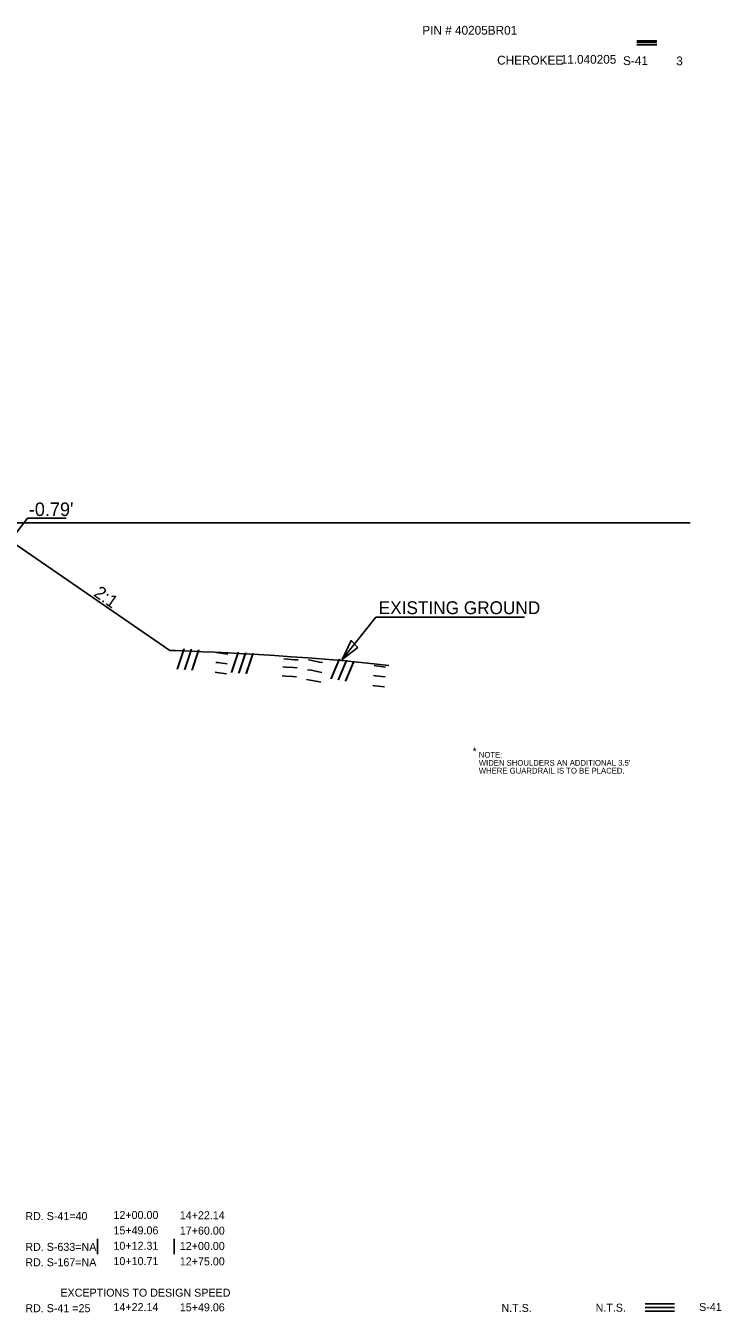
# Model space of a CAD drawing. Extents: x 2061536 to 2063199, y 948597 to 949645.
# Drawn here: x 2062634 to 2063199, y 948600 to 949645 of the extents above; entities that cross this region are included whole.
import ezdxf

# ---------------------------------------------------------------- set-up
doc = ezdxf.new("R2010")
doc.units = 0
for name, color, linetype in [('Default', 7, 'Continuous'), ('RD_SHT_Bndy', 7, 'Continuous'), ('RD_SHT_TX', 7, 'Continuous'), ('RD_TX_TypSect', 7, 'Continuous'), ('RD_XS_EarthShd', 7, 'Continuous')]:
    doc.layers.add(name, color=color, linetype=linetype)

msp = doc.modelspace()

# ---------------------------------------------------------------- linework, layer by layer
at = {"layer": 'Default'}
for p, q in [((2062555.4, 949240.8), (2063174, 949240.8)), ((2062635.8, 949244.7), (2062626.3, 949232)), ((2062635.8, 949244.7), (2062667.1, 949244.7)), ((2062891.5, 949129.9), (2062918.7, 949164.1)), ((2062918.7, 949164.1), (2063039.6, 949164.1))]:
    msp.add_line(p, q, dxfattribs=at)
msp.add_lwpolyline([(2062904.2, 949139.6), (2062891.5, 949129.9), (2062898.6, 949145.1)], close=True, dxfattribs=at)
for points in [[(2062789.3, 949135.4), (2062790.8, 949135.2), (2062798.6, 949134.2)], [(2062788.7, 949127.4), (2062790.2, 949127.2), (2062798.1, 949126.2)], [(2062843.2, 949123.9), (2062846.3, 949123.6), (2062851.8, 949123.2), (2062854.9, 949123)], [(2062844, 949130.3), (2062847.1, 949130), (2062852.6, 949129.6), (2062855.7, 949129.4)], [(2062863.2, 949121.5), (2062866.1, 949121), (2062872.4, 949119.8), (2062874.8, 949119.3)], [(2062864.1, 949129.5), (2062866.9, 949128.9), (2062873.1, 949127.7), (2062875.5, 949127.3)], [(2062917.4, 949124.8), (2062918.9, 949124.6), (2062926.7, 949123.6)], [(2062788.1, 949119.4), (2062789.7, 949119.2), (2062797.5, 949118.2)], [(2062842.6, 949116.5), (2062845.7, 949116.3), (2062851.2, 949115.9), (2062854.3, 949115.6)], [(2062862.4, 949113.6), (2062865.3, 949113), (2062871.6, 949111.8), (2062874, 949111.4)], [(2062916.8, 949116.8), (2062918.4, 949116.5), (2062926.2, 949115.6)], [(2062916.2, 949108.7), (2062917.8, 949108.5), (2062925.7, 949107.6)]]:
    msp.add_lwpolyline(points, dxfattribs=at)
msp.add_open_spline([(2062751.3, 949137.2), (2062769.7, 949136.6), (2062866.2, 949132.7), (2062929.2, 949124.9)], degree=3, dxfattribs=at)
at = {"layer": 'RD_SHT_Bndy'}
for p, q in [((2062692.5, 948646.7), (2062692.5, 948659.2)), ((2062755, 948646.7), (2062755, 948659.2))]:
    msp.add_line(p, q, dxfattribs=at)
at = {"layer": 'RD_TX_TypSect'}
for p, q in [((2063130.9, 949632.3), (2063146.9, 949632.3)), ((2063130.9, 949630.9), (2063146.9, 949630.9)), ((2063130.9, 949629), (2063146.9, 949629)), ((2063137.6, 948606.4), (2063161.3, 948606.4)), ((2063137.6, 948603.4), (2063161.3, 948603.4)), ((2063137.6, 948600.4), (2063161.3, 948600.4))]:
    msp.add_line(p, q, dxfattribs=at)
at = {"layer": 'RD_XS_EarthShd'}
msp.add_line((2062626.3, 949223.1), (2062751.3, 949137.2), dxfattribs=at)

# ---------------------------------------------------------------- texts
at = {"layer": 'Default'}
for s, height, p in [("-0.79'", 11, (2062636.8, 949246.3)), ('EXISTING GROUND', 10.45, (2062921.1, 949166.6)), ('*', 6.25, (2062997.4, 949052.1)), ("WIDEN SHOULDERS AN ADDITIONAL 3.5'", 4.687, (2063002.4, 949043.5)), ('NOTE:', 4.69, (2063002.4, 949050)), ('WHERE GUARDRAIL IS TO BE PLACED.', 4.687, (2063002.4, 949037.1))]:
    msp.add_text(s, height=height, dxfattribs=at).set_placement(p)
for height, rotation, p in [(16.1, 355.7741, (2062756.6, 949122.1)), (16.1, 355.378, (2062800.6, 949119.4)), (16.05, 351.2022, (2062881.5, 949114.3))]:
    msp.add_text('///', height=height, rotation=rotation, dxfattribs=at).set_placement(p)
at = {"layer": 'RD_SHT_TX'}
msp.add_text('EXCEPTIONS TO DESIGN SPEED', height=6.5, dxfattribs=at).set_placement((2062662.5, 948612.2))
at = {"layer": 'RD_TX_TypSect'}
for s, height, p in [('PIN # 40205BR01', 7.15, (2062956.5, 949637.3)), ('CHEROKEE', 7.15, (2063017.3, 949613)), ('11.040205', 7.15, (2063068.9, 949613.7)), ('S-41', 7.15, (2063119.6, 949612.6)), ('3', 7.15, (2063162.8, 949612.4)), ('RD. S-41=40', 6.5, (2062634, 948674.4)), ('12+00.00', 6.5, (2062705.6, 948675.3)), ('14+22.14', 6.5, (2062759.5, 948675.1)), ('15+49.06', 6.5, (2062705.6, 948662.8)), ('17+60.00', 6.5, (2062759.5, 948662.6)), ('RD. S-633=NA', 6.5, (2062634, 948649.4)), ('10+12.31', 6.5, (2062705.6, 948650.3)), ('12+00.00', 6.5, (2062759.5, 948650.1)), ('RD. S-167=NA', 6.5, (2062634, 948636.9)), ('10+10.71', 6.5, (2062705.6, 948637.8)), ('12+75.00', 6.5, (2062759.5, 948637.6)), ('RD. S-41 =25', 6.5, (2062634, 948599.6)), ('14+22.14', 6.5, (2062705.6, 948600.5)), ('15+49.06', 6.5, (2062759.5, 948600.3)), ('N.T.S.', 6.5, (2063020.8, 948599.8)), ('N.T.S.', 6.5, (2063097.3, 948600)), ('S-41', 6.5, (2063181.4, 948600.6))]:
    msp.add_text(s, height=height, dxfattribs=at).set_placement(p)
msp.add_text('2:1', height=10.31, rotation=324.8274, dxfattribs=at).set_placement((2062688.9, 949181.9))

doc.saveas('drawing.dxf')
